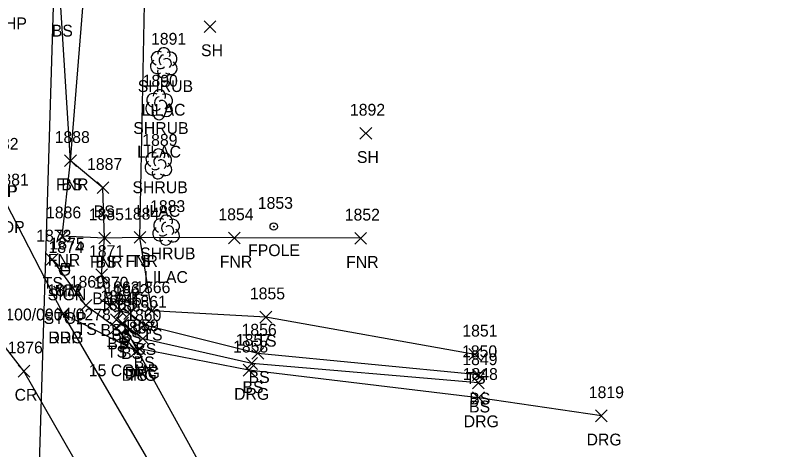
# Model space of a CAD drawing. Extents: x 1653908 to 1654393, y 539913 to 544256.
# Drawn here: x 1654097.1 to 1654225, y 541673.4 to 541747 of the extents above; entities that cross this region are included whole.
import ezdxf

# ---------------------------------------------------------------- set-up
doc = ezdxf.new("R2010")
doc.units = 0
for name, color, linetype in [('D_A', 7, 'Continuous'), ('D_C', 7, 'Continuous'), ('D_I', 7, 'Continuous'), ('D_TIC', 7, 'Continuous'), ('DCP', 7, 'Continuous'), ('L_A', 7, 'Continuous'), ('L_C', 7, 'Continuous'), ('L_I', 7, 'Continuous'), ('L_TIC', 7, 'Continuous'), ('LELB', 7, 'Continuous'), ('LFNC', 7, 'Continuous'), ('LFP', 7, 'Continuous'), ('LSH', 7, 'Continuous'), ('P_A', 7, 'Continuous'), ('P_I', 7, 'Continuous'), ('P_TIC', 7, 'Continuous'), ('PET', 7, 'Continuous'), ('PRC', 7, 'Continuous'), ('R_A', 7, 'Continuous'), ('R_I', 7, 'Continuous'), ('R_TIC', 7, 'Continuous'), ('RDG', 7, 'Continuous'), ('S_A', 7, 'Continuous'), ('S_C', 7, 'Continuous'), ('S_I', 7, 'Continuous'), ('SRM', 7, 'Continuous'), ('SSGN', 7, 'Continuous')]:
    doc.layers.add(name, color=color, linetype=linetype)

msp = doc.modelspace()

# ---------------------------------------------------------------- linework, layer by layer
at = {"layer": 'D_TIC'}
for points in [[(1654114.32, 541693.91), (1654116.32, 541695.91)], [(1654116.32, 541693.91), (1654114.32, 541695.91)]]:
    msp.add_lwpolyline(points, dxfattribs=at)
at = {"layer": 'DCP'}
for points in [[(1654099.93, 541626.87), (1654106.24, 541833.22)], [(1654134.74, 541659.61), (1654115.32, 541694.91)]]:
    msp.add_lwpolyline(points, dxfattribs=at)
at = {"layer": 'L_TIC'}
for points in [[(1654129.1, 541744.04), (1654131.1, 541746.04)], [(1654131.1, 541744.04), (1654129.1, 541746.04)], [(1654155.48, 541725.98), (1654157.48, 541727.98)], [(1654157.48, 541725.98), (1654155.48, 541727.98)], [(1654105.52, 541721.36), (1654107.52, 541723.36)], [(1654107.52, 541721.36), (1654105.52, 541723.36)], [(1654105.52, 541721.36), (1654107.52, 541723.36)], [(1654107.52, 541721.36), (1654105.52, 541723.36)], [(1654111, 541716.8), (1654113, 541718.8)], [(1654113, 541716.8), (1654111, 541718.8)], [(1654104.12, 541708.61), (1654106.12, 541710.61)], [(1654106.12, 541708.61), (1654104.12, 541710.61)], [(1654111.29, 541708.28), (1654113.29, 541710.28)], [(1654113.29, 541708.28), (1654111.29, 541710.28)], [(1654111.29, 541708.28), (1654113.29, 541710.28)], [(1654113.29, 541708.28), (1654111.29, 541710.28)], [(1654117.26, 541708.4), (1654119.26, 541710.4)], [(1654119.26, 541708.4), (1654117.26, 541710.4)], [(1654117.26, 541708.4), (1654119.26, 541710.4)], [(1654119.26, 541708.4), (1654117.26, 541710.4)], [(1654133.22, 541708.29), (1654135.22, 541710.29)], [(1654135.22, 541708.29), (1654133.22, 541710.29)], [(1654154.6, 541708.24), (1654156.6, 541710.24)], [(1654156.6, 541708.24), (1654154.6, 541710.24)], [(1654102.41, 541704.69), (1654104.41, 541706.69)], [(1654104.41, 541704.69), (1654102.41, 541706.69)], [(1654110.77, 541702.07), (1654112.77, 541704.07)], [(1654112.77, 541702.07), (1654110.77, 541704.07)], [(1654108.13, 541696.89), (1654110.13, 541698.89)], [(1654110.13, 541696.89), (1654108.13, 541698.89)], [(1654112.15, 541696.73), (1654114.15, 541698.73)], [(1654114.15, 541696.73), (1654112.15, 541698.73)], [(1654113.97, 541695.94), (1654115.97, 541697.94)], [(1654115.97, 541695.94), (1654113.97, 541697.94)], [(1654115.51, 541695.5), (1654117.51, 541697.5)], [(1654117.51, 541695.5), (1654115.51, 541697.5)], [(1654119.26, 541695.96), (1654121.26, 541697.96)], [(1654121.26, 541695.96), (1654119.26, 541697.96)], [(1654113.3, 541694.44), (1654115.3, 541696.44)], [(1654115.3, 541694.44), (1654113.3, 541696.44)], [(1654138.55, 541694.91), (1654140.55, 541696.91)], [(1654140.55, 541694.91), (1654138.55, 541696.91)], [(1654113.25, 541693.07), (1654115.25, 541695.07)], [(1654115.25, 541693.07), (1654113.25, 541695.07)], [(1654115.64, 541692.82), (1654117.64, 541694.82)], [(1654117.64, 541692.82), (1654115.64, 541694.82)], [(1654115.64, 541692.82), (1654117.64, 541694.82)], [(1654117.64, 541692.82), (1654115.64, 541694.82)], [(1654118.02, 541693.52), (1654120.02, 541695.52)], [(1654120.02, 541693.52), (1654118.02, 541695.52)], [(1654117.75, 541691.25), (1654119.75, 541693.25)], [(1654119.75, 541691.25), (1654117.75, 541693.25)], [(1654116.67, 541689.13), (1654118.67, 541691.13)], [(1654118.67, 541689.13), (1654116.67, 541691.13)], [(1654137.2, 541688.77), (1654139.2, 541690.77)], [(1654139.2, 541688.77), (1654137.2, 541690.77)], [(1654173.93, 541688.61), (1654175.93, 541690.61)], [(1654175.93, 541688.61), (1654173.93, 541690.61)], [(1654136.17, 541687.06), (1654138.17, 541689.06)], [(1654138.17, 541687.06), (1654136.17, 541689.06)], [(1654174.53, 541685.13), (1654176.53, 541687.13)], [(1654176.53, 541685.13), (1654174.53, 541687.13)], [(1654174.5, 541683.78), (1654176.5, 541685.78)], [(1654176.5, 541683.78), (1654174.5, 541685.78)]]:
    msp.add_lwpolyline(points, dxfattribs=at)
at = {"layer": 'LELB'}
for points in [[(1654174.93, 541689.61), (1654139.55, 541695.91), (1654120.26, 541696.96), (1654118.26, 541709.4), (1654119.13, 541754.53), (1654123.16, 541779.53), (1654123.23, 541784.66), (1654125.65, 541798.48), (1654129.32, 541798.42)], [(1654113.15, 541697.73), (1654111.77, 541703.07), (1654112.29, 541709.28), (1654112, 541717.8), (1654106.52, 541722.36), (1654104.9, 541748.36)], [(1654117.67, 541690.13), (1654114.25, 541694.07), (1654109.13, 541697.89), (1654103.41, 541705.69)], [(1654175.53, 541686.13), (1654138.2, 541689.77), (1654119.02, 541694.52), (1654116.51, 541696.5), (1654114.97, 541696.94), (1654114.3, 541695.44), (1654116.64, 541693.82)], [(1654175.5, 541684.78), (1654137.17, 541688.06), (1654118.75, 541692.25), (1654116.64, 541693.82)]]:
    msp.add_lwpolyline(points, dxfattribs=at)
at = {"layer": 'LFNC'}
msp.add_lwpolyline([(1654155.6, 541709.24), (1654134.22, 541709.29), (1654118.26, 541709.4), (1654112.29, 541709.28), (1654105.12, 541709.61), (1654106.52, 541722.36), (1654109.38, 541758.08), (1654113.16, 541797.97)], dxfattribs=at)
at = {"layer": 'LFP'}
for radius in [0.625, 0.0833]:
    msp.add_circle((1654140.89, 541711.22), radius, dxfattribs=at)
at = {"layer": 'LSH'}
for p, q in [((1654122.26, 541738.98), (1654122.26, 541738.98)), ((1654122.26, 541738.98), (1654122.26, 541738.98)), ((1654121.5, 541731.89), (1654121.5, 541731.89)), ((1654121.5, 541731.89), (1654121.5, 541731.89)), ((1654121.36, 541721.87), (1654121.36, 541721.87)), ((1654121.36, 541721.87), (1654121.36, 541721.87)), ((1654122.66, 541710.68), (1654122.66, 541710.68)), ((1654122.66, 541710.68), (1654122.66, 541710.68))]:
    msp.add_line(p, q, dxfattribs=at)
for centre in [(1654122.31, 541740.41), (1654121.55, 541733.32), (1654121.41, 541723.3), (1654122.71, 541712.12)]:
    msp.add_arc(centre, 1.05, 335.5272, 180.9563, dxfattribs=at)
for centre, major_axis, ratio, start_param, end_param in [((1654121.47, 541739.65), (1.21, -0.51), 0.895232, 1.570796, 4.712389), ((1654123.3, 541739.56), (-1.14, -0.48), 0.949671, 1.570796, 4.712389), ((1654122.05, 541739.44), (-0.208, -0.792), 0.645439, 3.141593, 6.283185), ((1654122.76, 541738.81), (-0.5, 0.667), 0.989748, 3.141593, 6.283185), ((1654121.18, 541738.27), (0.58, -1.04), 0.959034, 3.141593, 6.283185), ((1654121.8, 541738.23), (-0.625, -0.083), 0.423636, 0, 3.141593), ((1654123.26, 541738.15), (-1.09, 0.79), 0.841452, 1.570796, 4.712389), ((1654122.26, 541737.48), (0.26, 1.06), 0.942809, 1.570796, 4.712389), ((1654120.71, 541732.56), (1.21, -0.51), 0.895232, 1.570796, 4.712389), ((1654121.29, 541732.35), (-0.208, -0.792), 0.645439, 3.141593, 6.283185), ((1654122.54, 541732.47), (-1.14, -0.48), 0.949671, 1.570796, 4.712389), ((1654120.42, 541731.18), (0.58, -1.04), 0.959034, 3.141593, 6.283185), ((1654122, 541731.72), (-0.5, 0.667), 0.989748, 3.141593, 6.283185), ((1654122.5, 541731.06), (-1.09, 0.79), 0.841452, 1.570796, 4.712389), ((1654121.5, 541730.39), (0.26, 1.06), 0.942809, 1.570796, 4.712389), ((1654121.04, 541731.14), (-0.625, -0.083), 0.423636, 0, 3.141593), ((1654120.57, 541722.54), (1.21, -0.51), 0.895232, 1.570796, 4.712389), ((1654121.15, 541722.33), (-0.208, -0.792), 0.645439, 3.141593, 6.283185), ((1654122.4, 541722.45), (-1.14, -0.48), 0.949671, 1.570796, 4.712389), ((1654120.28, 541721.16), (0.58, -1.04), 0.959034, 3.141593, 6.283185), ((1654121.86, 541721.7), (-0.5, 0.667), 0.989748, 3.141593, 6.283185), ((1654122.36, 541721.04), (-1.09, 0.79), 0.841452, 1.570796, 4.712389), ((1654121.36, 541720.37), (0.26, 1.06), 0.942809, 1.570796, 4.712389), ((1654120.9, 541721.12), (-0.625, -0.083), 0.423636, 0, 3.141593), ((1654121.87, 541711.35), (1.21, -0.51), 0.895232, 1.570796, 4.712389), ((1654123.71, 541711.27), (-1.14, -0.48), 0.949671, 1.570796, 4.712389), ((1654122.46, 541711.14), (-0.208, -0.792), 0.645439, 3.141593, 6.283185), ((1654123.16, 541710.52), (-0.5, 0.667), 0.989748, 3.141593, 6.283185), ((1654121.58, 541709.98), (0.58, -1.04), 0.959034, 3.141593, 6.283185), ((1654122.21, 541709.93), (-0.625, -0.083), 0.423636, 0, 3.141593), ((1654123.66, 541709.85), (-1.09, 0.79), 0.841452, 1.570796, 4.712389), ((1654122.66, 541709.18), (0.26, 1.06), 0.942809, 1.570796, 4.712389)]:
    msp.add_ellipse(centre, major_axis=major_axis, ratio=ratio, start_param=start_param, end_param=end_param, dxfattribs=at)
at = {"layer": 'P_TIC'}
for points in [[(1654104.28, 541695.47), (1654106.28, 541697.47)], [(1654106.28, 541695.47), (1654104.28, 541697.47)], [(1654097.63, 541685.77), (1654099.63, 541687.77)], [(1654099.63, 541685.77), (1654097.63, 541687.77)]]:
    msp.add_lwpolyline(points, dxfattribs=at)
at = {"layer": 'PET'}
msp.add_lwpolyline([(1654080.09, 541663.58), (1654083.55, 541666.57), (1654088.66, 541667.17), (1654094.47, 541664.84), (1654099.96, 541660.14), (1654111.9, 541663.59), (1654122.03, 541667.7), (1654105.28, 541696.47), (1654095.63, 541715.16), (1654094.46, 541721.21)], dxfattribs=at)
at = {"layer": 'PRC'}
msp.add_lwpolyline([(1654225.01, 541487.06), (1654204.16, 541517.09), (1654180.22, 541550.99), (1654156.18, 541588.24), (1654139.45, 541615.76), (1654117.3, 541653.68), (1654111.9, 541663.59), (1654098.63, 541686.77), (1654084.43, 541705.04)], dxfattribs=at)
at = {"layer": 'R_TIC'}
for points in [[(1654104.28, 541695.47), (1654106.28, 541697.47)], [(1654106.28, 541695.47), (1654104.28, 541697.47)], [(1654116.67, 541689.13), (1654118.67, 541691.13)], [(1654118.67, 541689.13), (1654116.67, 541691.13)], [(1654117.2, 541689.52), (1654119.2, 541691.52)], [(1654119.2, 541689.52), (1654117.2, 541691.52)], [(1654135.71, 541685.92), (1654137.71, 541687.92)], [(1654137.71, 541685.92), (1654135.71, 541687.92)], [(1654174.55, 541681.28), (1654176.55, 541683.28)], [(1654176.55, 541681.28), (1654174.55, 541683.28)], [(1654195.33, 541678.2), (1654197.33, 541680.2)], [(1654197.33, 541678.2), (1654195.33, 541680.2)]]:
    msp.add_lwpolyline(points, dxfattribs=at)
at = {"layer": 'RDG'}
msp.add_lwpolyline([(1654196.33, 541679.2), (1654175.55, 541682.28), (1654136.71, 541686.92), (1654118.2, 541690.52), (1654117.67, 541690.13), (1654105.28, 541696.47)], dxfattribs=at)
at = {"layer": 'SRM'}
msp.add_lwpolyline([(1654105.03, 541704.97), (1654106.28, 541704.97), (1654106.28, 541703.72), (1654105.03, 541703.72)], close=True, dxfattribs=at)
msp.add_circle((1654105.65, 541704.35), 0.0833, dxfattribs=at)
at = {"layer": 'SSGN'}
for p, q in [((1654103.86, 541704.6), (1654107.19, 541704.6)), ((1654105.51, 541703.77), (1654105.51, 541703.77))]:
    msp.add_line(p, q, dxfattribs=at)
msp.add_circle((1654105.51, 541703.77), 0.833, dxfattribs=at)

# ---------------------------------------------------------------- texts
at = {"layer": 'D_A'}
msp.add_text('P', height=2, dxfattribs=at).set_placement((1654114.7, 541689.91))
at = {"layer": 'D_C'}
msp.add_text('15 CGMP', height=2, dxfattribs=at).set_placement((1654109.61, 541685.91))
at = {"layer": 'D_I'}
msp.add_text('1845', height=2, dxfattribs=at).set_placement((1654112.63, 541697.91))
at = {"layer": 'L_A'}
for s, p in [('BS', (1654103.34, 541743.36)), ('SH', (1654128.59, 541740.04)), ('SHRUB', (1654117.89, 541733.98)), ('SHRUB', (1654117.13, 541726.89)), ('SH', (1654154.97, 541721.98)), ('FNR', (1654104.06, 541717.36)), ('BS', (1654104.96, 541717.36)), ('SHRUB', (1654116.99, 541716.87)), ('BS', (1654110.44, 541712.8)), ('SHRUB', (1654118.29, 541705.68)), ('FPOLE', (1654136.56, 541706.22)), ('FNR', (1654102.66, 541704.61)), ('FNR', (1654109.82, 541704.28)), ('BS', (1654110.73, 541704.28)), ('FNR', (1654115.8, 541704.4)), ('TS', (1654116.67, 541704.4)), ('FNR', (1654131.76, 541704.29)), ('FNR', (1654153.14, 541704.24)), ('TS', (1654101.82, 541700.69)), ('BS', (1654110.21, 541698.07)), ('TS', (1654107.54, 541692.89)), ('BS', (1654111.59, 541692.73)), ('BS', (1654113.41, 541691.94)), ('BS', (1654114.96, 541691.5)), ('TS', (1654118.67, 541691.96)), ('BS', (1654112.74, 541690.44)), ('TS', (1654137.96, 541690.91)), ('TS', (1654112.66, 541689.07)), ('BS', (1654115.08, 541688.82)), ('BS', (1654115.08, 541688.82)), ('BS', (1654117.46, 541689.52)), ('BS', (1654117.19, 541687.25)), ('TS', (1654116.08, 541685.13)), ('BS', (1654136.64, 541684.77)), ('TS', (1654173.34, 541684.61)), ('BS', (1654135.61, 541683.06)), ('BS', (1654173.97, 541681.13)), ('BS', (1654173.94, 541679.78))]:
    msp.add_text(s, height=2, dxfattribs=at).set_placement(p)
at = {"layer": 'L_C'}
for p in [(1654118.53, 541729.98), (1654117.78, 541722.89), (1654117.64, 541712.87), (1654118.94, 541701.68)]:
    msp.add_text('LILAC', height=2, dxfattribs=at).set_placement(p)
at = {"layer": 'L_I'}
for s, p in [('1891', (1654120.13, 541741.98)), ('1890', (1654118.72, 541734.89)), ('1892', (1654153.79, 541729.98)), ('1888', (1654103.83, 541725.36)), ('1888', (1654103.83, 541725.36)), ('1889', (1654118.66, 541724.87)), ('1887', (1654109.31, 541720.8)), ('1883', (1654119.97, 541713.68)), ('1853', (1654138.2, 541714.22)), ('1886', (1654102.37, 541712.61)), ('1885', (1654109.6, 541712.28)), ('1885', (1654109.6, 541712.28)), ('1884', (1654115.57, 541712.4)), ('1884', (1654115.57, 541712.4)), ('1854', (1654131.53, 541712.29)), ('1852', (1654152.91, 541712.24)), ('1873', (1654100.72, 541708.69)), ('1871', (1654109.64, 541706.07)), ('1869', (1654106.38, 541700.89)), ('1870', (1654110.37, 541700.73)), ('1863', (1654112.23, 541699.94)), ('1862', (1654113.77, 541699.5)), ('1866', (1654117.46, 541699.96)), ('1864', (1654111.56, 541698.44)), ('1855', (1654136.86, 541698.91)), ('1868', (1654111.51, 541697.07)), ('1865', (1654113.9, 541696.82)), ('1865', (1654113.9, 541696.82)), ('1861', (1654116.85, 541697.52)), ('1860', (1654115.93, 541695.25)), ('1867', (1654114.93, 541693.13)), ('1856', (1654135.45, 541692.77)), ('1851', (1654172.8, 541692.61)), ('1857', (1654134.48, 541691.06)), ('1850', (1654172.75, 541689.13)), ('1849', (1654172.8, 541687.78))]:
    msp.add_text(s, height=2, dxfattribs=at).set_placement(p)
at = {"layer": 'P_A'}
for s, p in [('SHP', (1654093.64, 541744.59)), ('SHP', (1654091.99, 541716.21)), ('RDP', (1654091.95, 541716.21)), ('RDP', (1654093.11, 541710.16)), ('RDP', (1654102.77, 541691.47)), ('CR', (1654097.06, 541681.77))]:
    msp.add_text(s, height=2, dxfattribs=at).set_placement(p)
at = {"layer": 'P_I'}
for s, p in [('1882', (1654091.77, 541724.21)), ('1882', (1654091.77, 541724.21)), ('1881', (1654093.5, 541718.16)), ('1872', (1654102.59, 541699.47)), ('1876', (1654095.88, 541689.77))]:
    msp.add_text(s, height=2, dxfattribs=at).set_placement(p)
at = {"layer": 'R_A'}
for p in [(1654102.77, 541691.47), (1654115.16, 541685.13), (1654115.69, 541685.52), (1654134.19, 541681.92), (1654173.04, 541677.28), (1654193.82, 541674.2)]:
    msp.add_text('DRG', height=2, dxfattribs=at).set_placement(p)
at = {"layer": 'R_I'}
for s, p in [('1872', (1654102.59, 541699.47)), ('1867', (1654114.93, 541693.13)), ('1859', (1654115.5, 541693.52)), ('1858', (1654134.01, 541689.92)), ('1848', (1654172.86, 541685.28)), ('1819', (1654194.2, 541682.2))]:
    msp.add_text(s, height=2, dxfattribs=at).set_placement(p)
at = {"layer": 'S_A'}
for s, p in [('MM', (1654103.84, 541699.35)), ('SIGN', (1654102.64, 541698.75))]:
    msp.add_text(s, height=2, dxfattribs=at).set_placement(p)
at = {"layer": 'S_C'}
for s, p in [('1100/0904/0278', (1654094, 541695.35)), ('STOP', (1654101.97, 541694.75))]:
    msp.add_text(s, height=2, dxfattribs=at).set_placement(p)
at = {"layer": 'S_I'}
for s, p in [('1874', (1654102.79, 541706.75)), ('1875', (1654102.96, 541707.35))]:
    msp.add_text(s, height=2, dxfattribs=at).set_placement(p)

doc.saveas('drawing.dxf')
